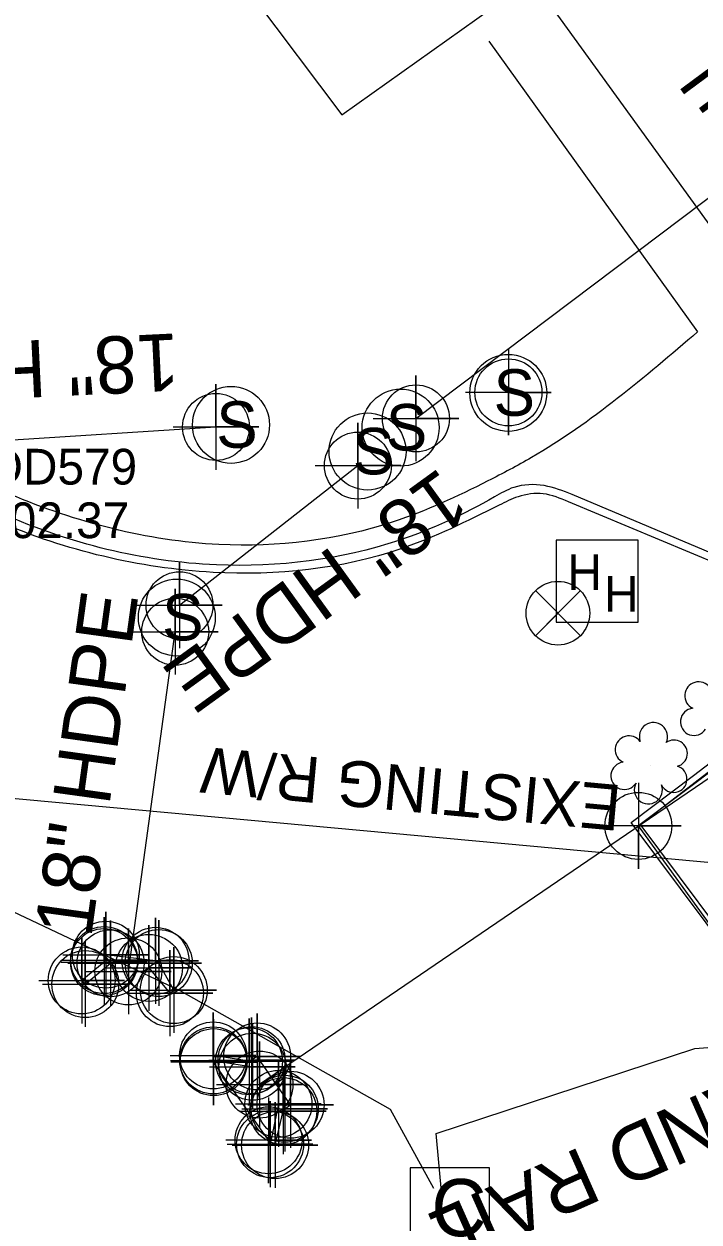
# Model space of a CAD drawing. Extents: x 1262092 to 1264624, y 774970 to 778314.
# Drawn here: x 1263459.5 to 1263506.8, y 776683.3 to 776767.1 of the extents above; entities that cross this region are included whole.
import ezdxf

# ---------------------------------------------------------------- set-up
doc = ezdxf.new("R2010")
doc.units = 0
for name, color, linetype in [('COGO Default Parcel', 7, 'Continuous'), ('Cogo Default Point CELL', 7, 'Continuous'), ('Exist Horizontal Alignment Tick Large', 7, 'Continuous'), ('Exist Other Culture Area Outline Cogo Point CELL', 7, 'Continuous'), ('Exist Other Culture Fence Line Cogo Point CELL', 7, 'Continuous'), ('Exist Other Culture Fence Line Text', 7, 'Continuous'), ('Exist Right of Way Line', 7, 'Continuous'), ('Exist Right of Way Line Text', 7, 'Continuous'), ('Exist Roads Curbs', 7, 'Continuous'), ('Exist Roads EOP', 7, 'Continuous'), ('Exist Roads EOT', 7, 'Continuous'), ('Exist Structure Major Bridge WW', 7, 'Continuous'), ('Exist Structure Major Bridge WW Cogo Point CELL', 7, 'Continuous'), ('Exist Structure Minor Head and End Wall', 7, 'Continuous'), ('Exist Structure Minor Head and End Wall Cogo Point CELL', 7, 'Continuous'), ('Exist Structure Minor Pipes CMP 72 Inch Cogo Point CELL', 7, 'Continuous'), ('Exist Structure Minor Pipes HDPE 18 Inch', 7, 'Continuous'), ('Exist Structure Minor Pipes HDPE 18 Inch Cogo Point CELL', 7, 'Continuous'), ('Exist Structure Minor Pipes HDPE 18 Inch Text', 7, 'Continuous'), ('Exist Structure Minor Pipes HDPE 24 Inch', 7, 'Continuous'), ('Exist Structure Minor Pipes HDPE 24 Inch Cogo Point CELL', 7, 'Continuous'), ('Exist Structure Minor Storm Sewer Manhole CELL', 7, 'Continuous'), ('Exist Utilities Other Pole With Base Cogo Elevation', 7, 'Continuous'), ('Exist Utilities Other Pole With Base Cogo Number', 7, 'Continuous'), ('Exist Utilities Power Hand Hole CELL', 7, 'Continuous'), ('Exist Utilities Telephone UG Conduit SUE LOS B', 7, 'Continuous'), ('Exist Utilities TV Pedestal CELL', 7, 'Continuous'), ('Exist Utilities Water Valve CELL', 7, 'Continuous'), ('Prop Horizontal Alignment Tick Large', 7, 'Continuous'), ('Prop Superelevation Label', 7, 'Continuous')]:
    doc.layers.add(name, color=color, linetype=linetype)

# ---------------------------------------------------------------- blocks, each defined once
blk = doc.blocks.new('EXIST UTILITIES TV PEDESTAL')
at = {"layer": 'Exist Utilities TV Pedestal CELL'}
blk.add_line((0, 0), (0, 0), dxfattribs=at)
blk.add_lwpolyline([(-0.0555, -0.0555), (0.0555, -0.0555), (0.0555, 0.0555), (-0.0555, 0.0555), (-0.0555, -0.0555)], dxfattribs=at)
blk.add_text('C', height=0.08, dxfattribs=at).set_placement((-0.0261, -0.04))

msp = doc.modelspace()

# ---------------------------------------------------------------- linework, layer by layer
at = {"layer": 'COGO Default Parcel'}
for p, q in [((1262441.327, 778142.766), (1263481.782, 776760.764)), ((1263481.782, 776760.764), (1263626.696, 776863.978))]:
    msp.add_line(p, q, dxfattribs=at)
at = {"layer": 'Cogo Default Point CELL'}
for points in [[(1263476.013, 776695.928), (1263476.013, 776692.928)], [(1263476.013, 776695.928), (1263476.013, 776692.928)], [(1263473.013, 776692.928), (1263476.013, 776692.928)], [(1263473.013, 776692.928), (1263476.013, 776692.928)], [(1263476.013, 776692.928), (1263479.013, 776692.928)], [(1263476.013, 776692.928), (1263476.013, 776689.928)], [(1263476.013, 776692.928), (1263479.013, 776692.928)], [(1263476.013, 776692.928), (1263476.013, 776689.928)]]:
    msp.add_lwpolyline(points, dxfattribs=at)
msp.add_circle((1263476.013, 776692.928), 2.344, dxfattribs=at)
msp.add_circle((1263476.013, 776692.928), 2.344, dxfattribs=at)
at = {"layer": 'Exist Horizontal Alignment Tick Large'}
msp.add_line((1263503.37, 776715.229), (1263503.37, 776715.229), dxfattribs=at)
for centre, radius, start, end in [((1263506.756, 776720.134), 0.968, 35.89076, 245.42165), ((1263506.439, 776718.303), 0.955, 95.10992, 327.95341), ((1263503.599, 776717.269), 0.99, 334.83907, 200.47174), ((1263501.887, 776716.356), 0.968, 35.89076, 245.42165), ((1263505.042, 776716.098), 0.929, 284.45672, 126.08612), ((1263501.57, 776714.525), 0.955, 95.10992, 327.95341), ((1263505.007, 776714.3), 0.937, 204.99133, 73.46012), ((1263503.242, 776713.545), 0.984, 151.27966, 21.38702)]:
    msp.add_arc(centre, radius, start, end, dxfattribs=at)
at = {"layer": 'Exist Other Culture Area Outline Cogo Point CELL'}
for points in [[(1263472.802, 776697.492), (1263472.802, 776691.492), (1263472.802, 776694.492), (1263475.802, 776694.492), (1263469.802, 776694.492)], [(1263476.647, 776692.024), (1263476.647, 776686.024), (1263476.647, 776689.024), (1263479.647, 776689.024), (1263473.647, 776689.024)]]:
    msp.add_lwpolyline(points, dxfattribs=at)
for centre in [(1263472.802, 776694.492), (1263476.647, 776689.024)]:
    msp.add_circle(centre, 2.344, dxfattribs=at)
at = {"layer": 'Exist Other Culture Fence Line Cogo Point CELL'}
msp.add_lwpolyline([(1263502.54, 776714.026), (1263502.54, 776708.026), (1263502.54, 776711.026), (1263505.54, 776711.026), (1263499.54, 776711.026)], dxfattribs=at)
msp.add_circle((1263502.54, 776711.026), 2.344, dxfattribs=at)
at = {"layer": 'Exist Right of Way Line'}
msp.add_line((1263428.45, 776715.752), (1263533.837, 776706.053), dxfattribs=at)
at = {"layer": 'Exist Roads Curbs'}
for points in [[(1263533.18, 776744.299), (1263531.434, 776740.22), (1263530.979, 776739.735), (1263537.388, 776731.369), (1263533.48, 776728.336), (1263509.517, 776710.172), (1263512.281, 776706.439), (1263544.592, 776723.757), (1263556.623, 776719.716), (1263555.196, 776715.025), (1263545.862, 776718.255), (1263545.519, 776718.647), (1263515.11, 776702.663), (1263510.853, 776700.186), (1263502.666, 776711.153), (1263506.67, 776714.16), (1263530.561, 776732.281), (1263527.087, 776736.865), (1263514.459, 776727.231), (1263497.911, 776734.212)], [(1263545.797, 776718.175), (1263544.619, 776717.591), (1263515.415, 776702.173), (1263510.74, 776699.624), (1263502.046, 776711.25), (1263506.398, 776714.548), (1263529.821, 776732.428), (1263526.963, 776736.025), (1263514.645, 776726.601), (1263497.646, 776733.689)]]:
    msp.add_lwpolyline(points, dxfattribs=at)
for points in [[(1263497.911, 776734.212), (1263495.937, 776734.829), (1263493.822, 776734.706), (1263492.464, 776734.036), (1263485.774, 776730.997), (1263472.998, 776729.285), (1263458.019, 776732.867), (1263450.747, 776736.721), (1263446.63, 776739.491), (1263444.227, 776741.776), (1263442.926, 776742.433), (1263441.298, 776742.218), (1263440.316, 776741.553), (1263438.962, 776739.662)], [(1263497.646, 776733.689), (1263495.88, 776734.259), (1263494.122, 776734.054), (1263492.784, 776733.463), (1263485.919, 776730.412), (1263472.759, 776728.763), (1263457.743, 776732.307), (1263450.531, 776736.082), (1263446.249, 776739.164), (1263443.785, 776741.344), (1263442.812, 776741.845), (1263441.693, 776741.727), (1263440.702, 776741.127), (1263439.535, 776739.594)]]:
    msp.add_spline(points, degree=3, dxfattribs=at)
at = {"layer": 'Exist Roads EOP'}
for p, q in [((1263510.738, 776748.621), (1263496.119, 776768.859)), ((1263492.071, 776765.919), (1263506.692, 776745.598))]:
    msp.add_line(p, q, dxfattribs=at)
msp.add_spline([(1263506.692, 776745.598), (1263495.067, 776736.799), (1263492.005, 776735.161), (1263485.372, 776732.296), (1263473.174, 776730.71), (1263458.556, 776734.218), (1263451.492, 776737.886), (1263447.381, 776740.823), (1263445.062, 776742.75), (1263443.201, 776743.771), (1263440.638, 776743.201), (1263439.485, 776742.575), (1263437.803, 776740.224)], degree=3, dxfattribs=at)
at = {"layer": 'Exist Roads EOT'}
msp.add_spline([(1263395.264, 776641.627), (1263402.689, 776638.748), (1263417.669, 776635.181), (1263446.829, 776640.835), (1263468.357, 776650.865), (1263499.886, 776667.729), (1263533.823, 776688.545)], degree=3, dxfattribs=at)
at = {"layer": 'Exist Structure Major Bridge WW'}
msp.add_lwpolyline([(1263468.272, 776701.087), (1263469.744, 776699.321), (1263470.012, 776699.533), (1263468.96, 776701.426), (1263468.733, 776701.582), (1263465.252, 776702.013), (1263465.135, 776701.637), (1263465.127, 776701.493), (1263463.563, 776700.206), (1263463.816, 776699.955), (1263465.587, 776701.412)], dxfattribs=at)
at = {"layer": 'Exist Structure Major Bridge WW Cogo Point CELL'}
for points in [[(1263462.252, 776702.013), (1263468.252, 776702.013), (1263465.252, 776702.013), (1263465.252, 776705.013), (1263465.252, 776699.013)], [(1263462.127, 776701.493), (1263468.127, 776701.493), (1263465.127, 776701.493), (1263465.127, 776704.493), (1263465.127, 776698.493)], [(1263462.135, 776701.637), (1263468.135, 776701.637), (1263465.135, 776701.637), (1263465.135, 776704.637), (1263465.135, 776698.637)], [(1263462.587, 776701.412), (1263468.587, 776701.412), (1263465.587, 776701.412), (1263465.587, 776704.412), (1263465.587, 776698.412)], [(1263465.272, 776701.087), (1263471.272, 776701.087), (1263468.272, 776701.087), (1263468.272, 776704.087), (1263468.272, 776698.087)], [(1263465.733, 776701.582), (1263471.733, 776701.582), (1263468.733, 776701.582), (1263468.733, 776704.582), (1263468.733, 776698.582)], [(1263465.96, 776701.426), (1263471.96, 776701.426), (1263468.96, 776701.426), (1263468.96, 776704.426), (1263468.96, 776698.426)], [(1263460.563, 776700.206), (1263466.563, 776700.206), (1263463.563, 776700.206), (1263463.563, 776703.206), (1263463.563, 776697.206)], [(1263460.816, 776699.955), (1263466.816, 776699.955), (1263463.816, 776699.955), (1263463.816, 776702.955), (1263463.816, 776696.955)], [(1263466.744, 776699.321), (1263472.744, 776699.321), (1263469.744, 776699.321), (1263469.744, 776702.321), (1263469.744, 776696.321)], [(1263467.012, 776699.533), (1263473.012, 776699.533), (1263470.012, 776699.533), (1263470.012, 776702.533), (1263470.012, 776696.533)]]:
    msp.add_lwpolyline(points, dxfattribs=at)
for centre in [(1263465.135, 776701.637), (1263465.252, 776702.013), (1263465.127, 776701.493), (1263465.587, 776701.412), (1263468.272, 776701.087), (1263468.733, 776701.582), (1263468.96, 776701.426), (1263463.563, 776700.206), (1263463.816, 776699.955), (1263469.744, 776699.321), (1263470.012, 776699.533)]:
    msp.add_circle(centre, 2.344, dxfattribs=at)
at = {"layer": 'Exist Structure Minor Head and End Wall'}
msp.add_lwpolyline([(1263477.335, 776691.575), (1263476.752, 776688.754), (1263477.102, 776688.694), (1263477.681, 776691.064), (1263477.777, 776691.234), (1263478.187, 776691.509), (1263475.848, 776694.891), (1263475.46, 776694.628), (1263475.278, 776694.552), (1263472.766, 776694.967), (1263472.777, 776694.617), (1263475.517, 776694.174)], dxfattribs=at)
at = {"layer": 'Exist Structure Minor Head and End Wall Cogo Point CELL'}
for points in [[(1263469.766, 776694.967), (1263475.766, 776694.967), (1263472.766, 776694.967), (1263472.766, 776697.967), (1263472.766, 776691.967)], [(1263469.777, 776694.617), (1263475.777, 776694.617), (1263472.777, 776694.617), (1263472.777, 776697.617), (1263472.777, 776691.617)], [(1263472.278, 776694.552), (1263478.278, 776694.552), (1263475.278, 776694.552), (1263475.278, 776697.552), (1263475.278, 776691.552)], [(1263472.46, 776694.628), (1263478.46, 776694.628), (1263475.46, 776694.628), (1263475.46, 776697.628), (1263475.46, 776691.628)], [(1263472.848, 776694.891), (1263478.848, 776694.891), (1263475.848, 776694.891), (1263475.848, 776697.891), (1263475.848, 776691.891)], [(1263472.517, 776694.174), (1263478.517, 776694.174), (1263475.517, 776694.174), (1263475.517, 776697.174), (1263475.517, 776691.174)], [(1263474.335, 776691.575), (1263480.335, 776691.575), (1263477.335, 776691.575), (1263477.335, 776694.575), (1263477.335, 776688.575)], [(1263474.681, 776691.064), (1263480.681, 776691.064), (1263477.681, 776691.064), (1263477.681, 776694.064), (1263477.681, 776688.064)], [(1263474.777, 776691.234), (1263480.777, 776691.234), (1263477.777, 776691.234), (1263477.777, 776694.234), (1263477.777, 776688.234)], [(1263475.187, 776691.509), (1263481.187, 776691.509), (1263478.187, 776691.509), (1263478.187, 776694.509), (1263478.187, 776688.509)], [(1263473.752, 776688.754), (1263479.752, 776688.754), (1263476.752, 776688.754), (1263476.752, 776691.754), (1263476.752, 776685.754)], [(1263474.102, 776688.694), (1263480.102, 776688.694), (1263477.102, 776688.694), (1263477.102, 776691.694), (1263477.102, 776685.694)]]:
    msp.add_lwpolyline(points, dxfattribs=at)
for centre in [(1263472.766, 776694.967), (1263472.777, 776694.617), (1263475.278, 776694.552), (1263475.46, 776694.628), (1263475.517, 776694.174), (1263475.848, 776694.891), (1263477.335, 776691.575), (1263477.681, 776691.064), (1263477.777, 776691.234), (1263478.187, 776691.509), (1263476.752, 776688.754), (1263477.102, 776688.694)]:
    msp.add_circle(centre, 2.344, dxfattribs=at)
at = {"layer": 'Exist Structure Minor Pipes CMP 72 Inch Cogo Point CELL'}
msp.add_lwpolyline([(1263493.442, 776744.357), (1263493.442, 776738.357), (1263493.442, 776741.357), (1263496.442, 776741.357), (1263490.442, 776741.357)], dxfattribs=at)
msp.add_circle((1263493.442, 776741.357), 2.344, dxfattribs=at)
at = {"layer": 'Exist Structure Minor Pipes HDPE 18 Inch'}
for p, q in [((1263486.967, 776739.533), (1263537.308, 776777.457)), ((1263426.964, 776736.049), (1263472.966, 776738.934)), ((1263470.41, 776726.461), (1263482.901, 776736.236)), ((1263466.83, 776700.846), (1263470.11, 776724.607))]:
    msp.add_line(p, q, dxfattribs=at)
at = {"layer": 'Exist Structure Minor Pipes HDPE 18 Inch Cogo Point CELL'}
for points in [[(1263483.967, 776739.533), (1263489.967, 776739.533), (1263486.967, 776739.533), (1263486.967, 776742.533), (1263486.967, 776736.533)], [(1263469.966, 776738.934), (1263475.966, 776738.934), (1263472.966, 776738.934), (1263472.966, 776741.934), (1263472.966, 776735.934)], [(1263479.901, 776736.236), (1263485.901, 776736.236), (1263482.901, 776736.236), (1263482.901, 776739.236), (1263482.901, 776733.236)], [(1263467.41, 776726.461), (1263473.41, 776726.461), (1263470.41, 776726.461), (1263470.41, 776729.461), (1263470.41, 776723.461)], [(1263467.11, 776724.607), (1263473.11, 776724.607), (1263470.11, 776724.607), (1263470.11, 776727.607), (1263470.11, 776721.607)], [(1263463.83, 776700.846), (1263469.83, 776700.846), (1263466.83, 776700.846), (1263466.83, 776703.846), (1263466.83, 776697.846)]]:
    msp.add_lwpolyline(points, dxfattribs=at)
for centre in [(1263486.967, 776739.533), (1263472.966, 776738.934), (1263482.901, 776736.236), (1263470.41, 776726.461), (1263470.11, 776724.607), (1263466.83, 776700.846)]:
    msp.add_circle(centre, 2.344, dxfattribs=at)
at = {"layer": 'Exist Structure Minor Pipes HDPE 24 Inch'}
msp.add_line((1263592.591, 776772.324), (1263476.013, 776692.928), dxfattribs=at)
at = {"layer": 'Exist Structure Minor Pipes HDPE 24 Inch Cogo Point CELL'}
msp.add_lwpolyline([(1263473.013, 776692.928), (1263479.013, 776692.928), (1263476.013, 776692.928), (1263476.013, 776695.928), (1263476.013, 776689.928)], dxfattribs=at)
msp.add_circle((1263476.013, 776692.928), 2.344, dxfattribs=at)
at = {"layer": 'Exist Structure Minor Storm Sewer Manhole CELL'}
for centre in [(1263493.433, 776741.321), (1263474.019, 776739.081), (1263485.892, 776738.89), (1263483.578, 776737.219), (1263470.223, 776725.602)]:
    msp.add_circle(centre, 2.694, dxfattribs=at)
at = {"layer": 'Exist Utilities Power Hand Hole CELL'}
msp.add_line((1263499.733, 776727.995), (1263499.733, 776727.995), dxfattribs=at)
msp.add_lwpolyline([(1263496.783, 776725.27), (1263502.533, 776725.27), (1263502.533, 776731.02), (1263496.783, 776731.02), (1263496.783, 776725.27)], dxfattribs=at)
at = {"layer": 'Exist Utilities Telephone UG Conduit SUE LOS B'}
for points in [[(1263488.217, 776685.663), (1263485.191, 776691.171), (1263470.506, 776699.448), (1263417.859, 776724.336), (1263408.185, 776729.024)], [(1263488.778, 776685.19), (1263488.394, 776689.501), (1263506.493, 776695.456), (1263517.621, 776696.308), (1263533.542, 776703.199), (1263540.296, 776703.396)]]:
    msp.add_lwpolyline(points, dxfattribs=at)
at = {"layer": 'Exist Utilities Water Valve CELL'}
msp.add_lwpolyline([(1263498.483, 776727.482), (1263495.333, 776724.332), (1263496.908, 776725.907), (1263498.483, 776724.332), (1263495.333, 776727.482)], dxfattribs=at)
msp.add_circle((1263496.908, 776725.907), 2.227, dxfattribs=at)
at = {"layer": 'Prop Horizontal Alignment Tick Large'}
msp.add_lwpolyline([(1263543.745, 776717.373), (1263510.76, 776699.698), (1263502.54, 776711.026), (1263530.328, 776732.422), (1263529.55, 776733.192)], dxfattribs=at)
at = {"layer": 'Prop Superelevation Label'}
msp.add_line((1263476.647, 776689.024), (1263472.802, 776694.492), dxfattribs=at)

# ---------------------------------------------------------------- block references
at = {"layer": 'Exist Utilities TV Pedestal CELL', "xscale": 50, "yscale": 50}
msp.add_blockref('EXIST UTILITIES TV PEDESTAL', (1263489.346, 776684.315), dxfattribs=at)

# ---------------------------------------------------------------- texts
at = {"layer": 'Exist Other Culture Fence Line Text'}
msp.add_text('2 RAIL HAND RAIL', height=4, rotation=203.90613, dxfattribs=at).set_placement((1263530.053, 776702.595))
at = {"layer": 'Exist Right of Way Line Text'}
msp.add_text('EXISTING R/W', height=3.2, rotation=174.7417, dxfattribs=at).set_placement((1263501.438, 776713.855))
at = {"layer": 'Exist Structure Minor Pipes HDPE 18 Inch Text'}
for rotation, p in [(216.50641, (1263524.742, 776776.824)), (182.75169, (1263470.3, 776745.491)), (215.92302, (1263488.679, 776736.172)), (82.14049, (1263464.217, 776703.125))]:
    msp.add_text('18" HDPE', height=4, rotation=rotation, dxfattribs=at).set_placement(p)
at = {"layer": 'Exist Structure Minor Storm Sewer Manhole CELL'}
for p in [(1263492.402, 776739.721), (1263472.988, 776737.481), (1263484.861, 776737.29), (1263482.547, 776735.619), (1263469.192, 776724.002)]:
    msp.add_text('S', height=3.25, dxfattribs=at).set_placement(p)
at = {"layer": 'Exist Utilities Other Pole With Base Cogo Elevation'}
msp.add_text('1202.37', height=2.5, dxfattribs=at).set_placement((1263454.808, 776731.156))
at = {"layer": 'Exist Utilities Other Pole With Base Cogo Number'}
msp.add_text('ADD579', height=2.5, dxfattribs=at).set_placement((1263454.808, 776734.906))
at = {"layer": 'Exist Utilities Power Hand Hole CELL'}
for p in [(1263497.574, 776727.521), (1263500.138, 776726.001)]:
    msp.add_text('H', height=2.5, dxfattribs=at).set_placement(p)

doc.saveas('drawing.dxf')
